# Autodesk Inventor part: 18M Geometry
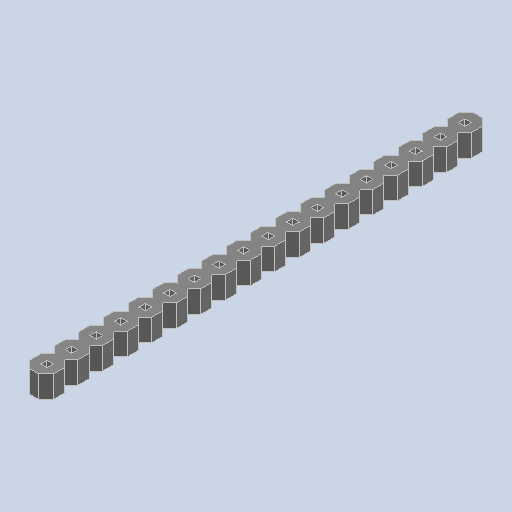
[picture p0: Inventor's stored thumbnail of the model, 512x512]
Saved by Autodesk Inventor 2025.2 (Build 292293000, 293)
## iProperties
Created: 2025-04
Part Number: 18M Geometry
Material: Generic
Description: PART-18M Geometry-DESC
Document SubType Name: Modeling
Designer: BennF
Density: 1 g/cm^3
Appearance: Default
Author: BennF
Revision Number: NONE
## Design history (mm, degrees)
feature "18"
body "Solid1"
